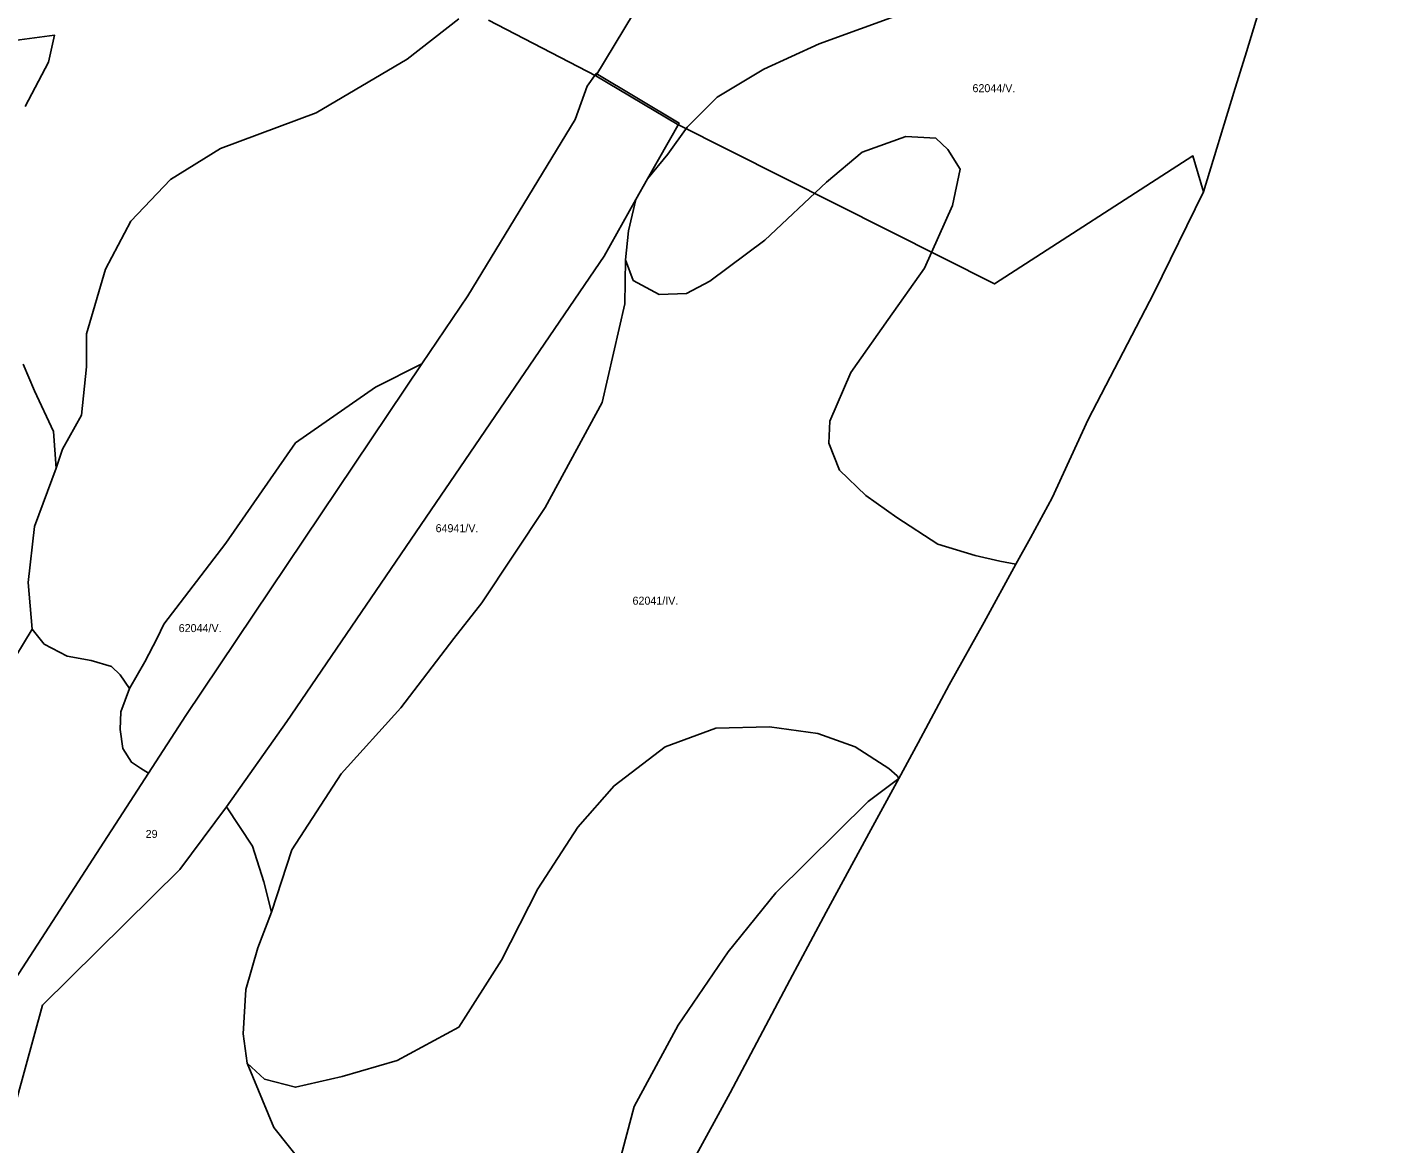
# Model space of a CAD drawing. Extents: x -521621 to -516761, y -1190184 to -1184927.
# Drawn here: x -517460 to -516777, y -1187492 to -1186934 of the extents above; entities that cross this region are included whole.
import ezdxf

# ---------------------------------------------------------------- set-up
doc = ezdxf.new("R2010")
doc.units = 0
doc.layers.add('BPEJ_s', color=7, linetype='Continuous')
doc.layers.add('odvodneni_s', color=7, linetype='Continuous')

msp = doc.modelspace()

# ---------------------------------------------------------------- linework, layer by layer
at = {"layer": 'BPEJ_s'}
for points in [[(-517003.71, -1186920.26), (-517063.94, -1186942.21), (-517091.49, -1186954.83), (-517114.83, -1186968.84), (-517129.77, -1186983.79), (-517139.58, -1186997.34), (-517149.58, -1187009.7), (-517133.86, -1186981.78), (-517175.27, -1186956.98), (-517179.84, -1186963.3), (-517185.8, -1186980.02), (-517239.52, -1187068.12), (-517262.4, -1187102.2), (-517285.6, -1187113.76), (-517325.49, -1187141.64), (-517360.32, -1187191.7), (-517391.35, -1187232.25), (-517394.62, -1187239.21), (-517400.89, -1187250.96), (-517408.54, -1187264.35), (-517413.18, -1187257.52), (-517417.55, -1187253.42), (-517427.65, -1187250.41), (-517439.66, -1187248.23), (-517451.13, -1187242.22), (-517457.21, -1187234.78), (-517459.11, -1187211.34), (-517455.94, -1187183.46), (-517445.18, -1187154.31), (-517442.01, -1187144.81), (-517432.51, -1187127.7), (-517429.98, -1187103.62), (-517429.98, -1187087.15), (-517420.48, -1187054.83), (-517407.81, -1187030.75), (-517388.08, -1187009.94), (-517362.97, -1186994.54), (-517315.17, -1186976.71), (-517269.81, -1186949.96), (-517243.89, -1186929.7)], [(-516844.56, -1186927.14), (-516850.39, -1186946.24), (-516856.6, -1186966.47), (-516871.88, -1187016.23), (-516896.58, -1187066.77), (-516929.39, -1187129.92), (-516947.5, -1187169.09), (-516958.34, -1187189), (-516965.57, -1187202.24), (-516973.59, -1187200.72), (-516985.93, -1187197.89), (-517004.64, -1187192.24), (-517025.1, -1187178.83), (-517040.63, -1187167.88), (-517053.69, -1187155.17), (-517058.98, -1187141.75), (-517058.63, -1187130.81), (-517048.04, -1187106.45), (-517029.39, -1187080.03), (-517011.18, -1187054.33), (-516997.18, -1187023.03), (-516993.44, -1187004.81), (-516999.51, -1186995), (-517005.58, -1186989.4), (-517020.52, -1186988.46), (-517042.46, -1186996.41), (-517060.21, -1187011.35), (-517091.02, -1187040.32), (-517118.57, -1187060.87), (-517130.24, -1187066.95), (-517143.78, -1187067.42), (-517156.85, -1187060.41), (-517160.59, -1187050.13), (-517159.18, -1187035.65), (-517155.41, -1187020.07), (-517149.58, -1187009.7), (-517139.58, -1186997.34), (-517129.77, -1186983.79), (-517114.83, -1186968.84), (-517091.49, -1186954.83), (-517063.94, -1186942.21), (-517003.71, -1186920.26)], [(-517243.89, -1186929.7), (-517269.81, -1186949.96), (-517315.17, -1186976.71), (-517362.97, -1186994.54), (-517388.08, -1187009.94), (-517407.81, -1187030.75), (-517420.48, -1187054.83), (-517429.98, -1187087.15), (-517429.98, -1187103.62), (-517432.51, -1187127.7), (-517442.01, -1187144.81), (-517445.18, -1187154.31), (-517446.44, -1187135.94), (-517455.94, -1187115.66), (-517461.64, -1187102.35)], [(-517470.99, -1186941.19), (-517445.99, -1186937.81), (-517449.03, -1186951.31), (-517460.58, -1186973.53)], [(-517470.99, -1186941.19), (-517445.99, -1186937.81), (-517449.03, -1186951.31), (-517460.58, -1186973.53)], [(-517510.08, -1187478.08), (-517399, -1187306.68), (-517380.36, -1187277.92), (-517262.4, -1187102.2), (-517239.52, -1187068.12), (-517185.8, -1186980.02), (-517179.84, -1186963.3), (-517175.27, -1186956.98), (-517133.86, -1186981.78), (-517149.58, -1187009.7), (-517155.41, -1187020.07), (-517171.29, -1187048.26), (-517329.96, -1187280.8), (-517359.97, -1187323.51), (-517383.4, -1187354.77), (-517451.95, -1187422.51), (-517469.3, -1187485.9)], [(-517461.64, -1187102.35), (-517455.94, -1187115.66), (-517446.44, -1187135.94), (-517445.18, -1187154.31), (-517455.94, -1187183.46), (-517459.11, -1187211.34), (-517457.21, -1187234.78), (-517469.69, -1187255.33)], [(-517469.69, -1187255.33), (-517457.21, -1187234.78), (-517451.13, -1187242.22), (-517439.66, -1187248.23), (-517427.65, -1187250.41), (-517417.55, -1187253.42), (-517413.18, -1187257.52), (-517408.54, -1187264.35), (-517412.91, -1187276.09), (-517413.18, -1187284.83), (-517411.82, -1187294.4), (-517407.45, -1187301.23), (-517403.08, -1187304.23), (-517399, -1187306.68), (-517510.08, -1187478.08)], [(-517312.9, -1187513.19), (-517336.32, -1187483.72), (-517349.7, -1187451.58), (-517341, -1187459.62), (-517325.61, -1187463.63), (-517302.19, -1187458.28), (-517274.75, -1187450.24), (-517243.97, -1187433.5), (-517222.55, -1187400.02), (-517204.48, -1187364.53), (-517184.41, -1187333.72), (-517166.34, -1187312.97), (-517140.91, -1187293.55), (-517115.47, -1187284.17), (-517088.71, -1187283.5), (-517064.61, -1187286.85), (-517045.87, -1187293.55), (-517029.14, -1187304.26), (-517024.84, -1187308.06), (-517024.06, -1187309.28), (-517039.43, -1187320.84), (-517085.49, -1187366.47), (-517109.43, -1187395.91), (-517134.4, -1187432.53), (-517156.28, -1187473.14), (-517169.51, -1187522.88)], [(-517469.3, -1187485.9), (-517451.95, -1187422.51), (-517383.4, -1187354.77), (-517359.97, -1187323.51), (-517347.02, -1187343.13), (-517341.32, -1187360.88), (-517337.52, -1187376.08), (-517344.35, -1187393.99), (-517350.37, -1187414.75), (-517351.71, -1187436.85), (-517349.7, -1187451.58), (-517336.32, -1187483.72), (-517312.9, -1187513.19)]]:
    msp.add_lwpolyline(points, dxfattribs=at)
for points in [[(-517349.7, -1187451.58), (-517351.71, -1187436.85), (-517350.37, -1187414.75), (-517344.35, -1187393.99), (-517337.52, -1187376.08), (-517327.39, -1187345.04), (-517302.7, -1187307.02), (-517272.93, -1187274.07), (-517246.46, -1187239.41), (-517232.41, -1187221.48), (-517200.74, -1187173.96), (-517172.25, -1187121.36), (-517161.05, -1187072.09), (-517160.59, -1187050.13), (-517156.85, -1187060.41), (-517143.78, -1187067.42), (-517130.24, -1187066.95), (-517118.57, -1187060.87), (-517091.02, -1187040.32), (-517060.21, -1187011.35), (-517042.46, -1186996.41), (-517020.52, -1186988.46), (-517005.58, -1186989.4), (-516999.51, -1186995), (-516993.44, -1187004.81), (-516997.18, -1187023.03), (-517011.18, -1187054.33), (-517029.39, -1187080.03), (-517048.04, -1187106.45), (-517058.63, -1187130.81), (-517058.98, -1187141.75), (-517053.69, -1187155.17), (-517040.63, -1187167.88), (-517025.1, -1187178.83), (-517004.64, -1187192.24), (-516985.93, -1187197.89), (-516973.59, -1187200.72), (-516965.57, -1187202.24), (-516981.42, -1187231.27), (-516998.89, -1187262.51), (-517014.39, -1187291.51), (-517024.06, -1187309.28), (-517024.84, -1187308.06), (-517029.14, -1187304.26), (-517045.87, -1187293.55), (-517064.61, -1187286.85), (-517088.71, -1187283.5), (-517115.47, -1187284.17), (-517140.91, -1187293.55), (-517166.34, -1187312.97), (-517184.41, -1187333.72), (-517204.48, -1187364.53), (-517222.55, -1187400.02), (-517243.97, -1187433.5), (-517274.75, -1187450.24), (-517302.19, -1187458.28), (-517325.61, -1187463.63), (-517341, -1187459.62)], [(-517359.97, -1187323.51), (-517329.96, -1187280.8), (-517171.29, -1187048.26), (-517155.41, -1187020.07), (-517159.18, -1187035.65), (-517160.59, -1187050.13), (-517161.05, -1187072.09), (-517172.25, -1187121.36), (-517200.74, -1187173.96), (-517232.41, -1187221.48), (-517246.46, -1187239.41), (-517272.93, -1187274.07), (-517302.7, -1187307.02), (-517327.39, -1187345.04), (-517337.52, -1187376.08), (-517341.32, -1187360.88), (-517347.02, -1187343.13)], [(-517408.54, -1187264.35), (-517400.89, -1187250.96), (-517394.62, -1187239.21), (-517391.35, -1187232.25), (-517360.32, -1187191.7), (-517325.49, -1187141.64), (-517285.6, -1187113.76), (-517262.4, -1187102.2), (-517380.36, -1187277.92), (-517399, -1187306.68), (-517403.08, -1187304.23), (-517407.45, -1187301.23), (-517411.82, -1187294.4), (-517413.18, -1187284.83), (-517412.91, -1187276.09)], [(-517187.86, -1187627.92), (-517188.2, -1187619.17), (-517187.75, -1187606.39), (-517180, -1187563.95), (-517169.51, -1187522.88), (-517156.28, -1187473.14), (-517134.4, -1187432.53), (-517109.43, -1187395.91), (-517085.49, -1187366.47), (-517039.43, -1187320.84), (-517024.06, -1187309.28), (-517038.01, -1187334.89), (-517060.45, -1187376.19), (-517068.28, -1187390.81), (-517078.57, -1187410.02), (-517095.03, -1187441.31), (-517108.3, -1187466.4), (-517127.2, -1187500.93), (-517117.98, -1187506.92), (-517119.44, -1187512.1), (-517126.72, -1187534.43), (-517128.98, -1187537.83), (-517162.09, -1187591.74), (-517181.17, -1187619.1)]]:
    msp.add_lwpolyline(points, close=True, dxfattribs=at)
at = {"layer": 'odvodneni_s'}
msp.add_lwpolyline([(-517229.06, -1186930.43), (-517175.45, -1186958.22), (-516954.83, -1186592.8)], dxfattribs=at)
msp.add_lwpolyline([(-516954.83, -1186592.8), (-517175.45, -1186958.22), (-517134.87, -1186982.42), (-516976.29, -1187062.17), (-516877.08, -1186998.25), (-516871.88, -1187016.23), (-516856.6, -1186966.47), (-516850.39, -1186946.24), (-516844.56, -1186927.14), (-516822.77, -1186861.25), (-516803.7, -1186796.3), (-516791.41, -1186724.89), (-516777.29, -1186712.47), (-516783.52, -1186685.16), (-516792.51, -1186656.77), (-516821.91, -1186586.88)], close=True, dxfattribs=at)

# ---------------------------------------------------------------- texts
at = {"layer": 'BPEJ_s'}
for s, p in [('62044/V.', (-516987.27, -1186966.38)), ('64941/V.', (-517255.55, -1187186.25)), ('62041/IV.', (-517157.15, -1187222.46)), ('62044/V.', (-517383.92, -1187236.17)), ('29', (-517400.43, -1187339.02))]:
    msp.add_text(s, height=4, dxfattribs=at).set_placement(p)

doc.saveas('drawing.dxf')
